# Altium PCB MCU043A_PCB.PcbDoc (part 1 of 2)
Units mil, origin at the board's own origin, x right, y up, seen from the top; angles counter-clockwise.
Board outline 3935 x 1020 mil, 2 copper layers (Top Layer, Bottom Layer), stack 62 mil thick; 69 components, 49 nets, 220 pads, 91 vias.
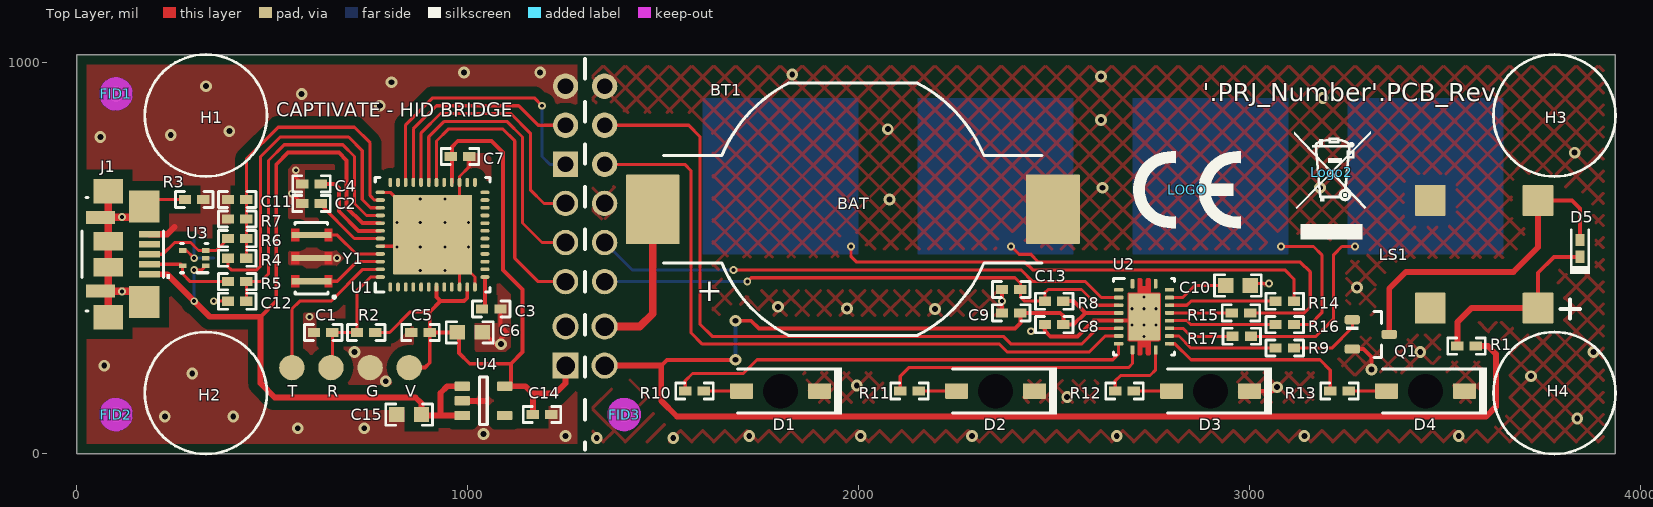
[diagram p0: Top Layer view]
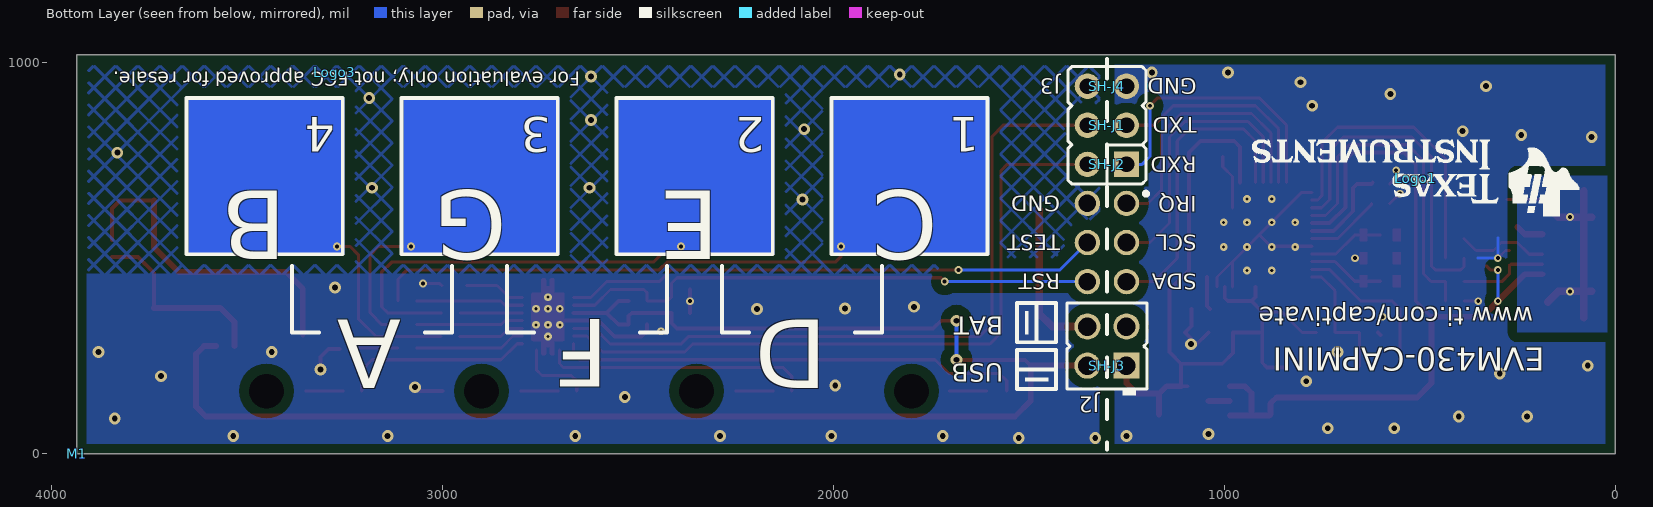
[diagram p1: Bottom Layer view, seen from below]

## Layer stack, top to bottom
Top Solder: solder mask 0.4, Solder Resist, Dk 3.5
Top Layer: signal copper 1.4
Dielectric1: core 59.2, FR-4, Dk 4.8
Bottom Layer: signal copper 1.4
Bottom Solder: solder mask 0.4, Solder Resist, Dk 3.5

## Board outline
0,0 3935,0 3935,1020 0,1020

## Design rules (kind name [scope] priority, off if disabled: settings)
AcuteAngle [All] p1: minimum=4.50000000000000E+0001 checktracksonly=FALSE
AssemblyTestPointUsage [All] p1: valid=2
BoardOutlineClearance BoardOutlineClearance_MountingHoles [OnCopper and InComponentClass('Mounting Holes')] p1: gap=40
BoardOutlineClearance BoardOutlineClearance_Poly [OnCopper and IsPoly] p2: gap=25
BoardOutlineClearance [OnCopper and Not InComponentClass('Logo') and not InComponentClass('FiducialMark') and not InRegion(1000,500,4000,800) and not InPoly] p3: gap=20
Clearance Clearance_Keepouts [((IsTrack Or IsArc) And Not InPoly) And IsFree and IsKeepOut vs ((IsTrack Or IsArc) And Not InPoly) And IsFree and IsKeepOut] p1: gap=0
Clearance Clearance_Fid [HasFootprint('Fiducial10-20')] p2: gap=0
Clearance Clearance_Poly [InPolygon] p3: gap=25
Clearance [All] p4: gap=7.87
ComponentClearance ComponentClearance-Fid [HasFootprint('Fiducial10-20')] p1: gap=10 collisioncheckmode=3 verticalgap=0 showdistances=FALSE
ComponentClearance ComponentClearance-Overlay [HasFootprint('EVM430-CAPMINI-OVERLAY-PMMA')] p2: gap=0 collisioncheckmode=3 verticalgap=0 showdistances=FALSE
ComponentClearance ComponentClearance-Jumper [HasFootprint('SPC02SYAN')] p3: gap=5 collisioncheckmode=3 verticalgap=0 showdistances=FALSE
ComponentClearance ComponentClearance_MountingHoles_FiducialMarks [InComponentClass('Mounting Holes') vs InComponentClass('FiducialMark')] p4: gap=50 collisioncheckmode=3 verticalgap=10 showdistances=FALSE
ComponentClearance ComponentClearance_Shunt [InComponentClass('Header') vs InComponentClass('Shunt')] p5: gap=0 collisioncheckmode=3 verticalgap=0 showdistances=FALSE
ComponentClearance ComponentClearance_Logo [InComponentClass('Logo')] p6: gap=50 collisioncheckmode=3 verticalgap=10 showdistances=FALSE
ComponentClearance ComponentClearance_ScrewToNut [(HasFootprint('NY PMS 440 0025 PH')) vs (HasFootprint('Keystone_1902C'))] p7: gap=5 collisioncheckmode=3 verticalgap=10 showdistances=FALSE
ComponentClearance ComponentClearance_MountingHoles [InComponentClass('Mounting Holes')] p8: gap=250 collisioncheckmode=3 verticalgap=100000 showdistances=FALSE
ComponentClearance ComponentClearance_SmallPassives [HasFootprint('0201*') or HasFootprint('0402*') or HasFootprint('0508') or HasFootprint('0603*') or HasFootprint('0612') or HasFootprint('0805*') or HasFootprint('0815*') or HasFootprint('0830*') or HasFootprint('1206*') or HasFootprint('1210*') or HasFootprint('1808*') or HasFootprint('1812*') or HasFootprint('1825*') or HasFootprint('2010*') or HasFootprint('2220*') or HasFootprint('2225*') or HasFootprint('2512*') or HasFootprint('2728*') or HasFootprint('3518*') vs HasFootprint('0201*') or HasFootprint('0402*') or HasFootprint('0508') or HasFootprint('0603*') or HasFootprint('0612') or HasFootprint('0805*') or HasFootprint('0815*') or HasFootprint('0830*') or HasFootprint('1206*') or HasFootprint('1210*') or HasFootprint('1808*') or HasFootprint('1812*') or HasFootprint('1825*') or HasFootprint('2010*') or HasFootprint('2220*') or HasFootprint('2225*') or HasFootprint('2512*') or HasFootprint('2728*') or HasFootprint('3518*')] p9: gap=14.96 collisioncheckmode=3 verticalgap=10 showdistances=FALSE
ComponentClearance ComponentClearance_THtoSMT [IsThruComponent vs IsSMTComponent] p10: gap=40 collisioncheckmode=3 verticalgap=30 showdistances=FALSE
ComponentClearance ComponentClearance_THtoTH [IsThruComponent vs IsThruComponent] p11: gap=30 collisioncheckmode=3 verticalgap=30 showdistances=FALSE
ComponentClearance [All] p12: gap=30 collisioncheckmode=3 verticalgap=10 showdistances=FALSE
DiffPairsRouting [All] p1: maxlimit=100 minlimit=10 mostfreqgap=10 toplayer_minwidth=15 toplayer_maxwidth=15 toplayer_prefwidth=15 bottomlayer_minwidth=15 bottomlayer_maxwidth=15 bottomlayer_prefwidth=15 maxuncoupledlength=1000
FabricationTestPointUsage TestPointUsage [All] p1: valid=2 allowmultiple=FALSE
FabricationTestpoint Testpoint [All] p1: side=3 testpointundercomponent=TRUE minsize=40 maxsize=100 preferedsize=60 minholesize=0 maxholesize=40 preferedholesize=32 testpointgrid=1 allowsidetop=TRUE allowsidebottom=TRUE usegrid=TRUE gridtolerance=0.01
FanoutControl Fanout_LCC [IsLCC] p1: bgadir=Out bgaviamode=Centered fanoutstyle=Auto fanoutdirection=Alternating viagrid=1 // Fanout_LCC (Default Rule)
FanoutControl Fanout_BGA [IsBGA] p2: bgadir=Out bgaviamode=Centered fanoutstyle=Auto fanoutdirection=Alternating viagrid=1 // Fanout_BGA (Default Rule)
FanoutControl Fanout_Default [All] p4: bgadir=Out bgaviamode=Centered fanoutstyle=Auto fanoutdirection=Alternating viagrid=1 // Fanout_Default (Default Rule)
FanoutControl Fanout_Small [(CompPinCount < 5)] p5: bgadir=Out bgaviamode=Centered fanoutstyle=Auto fanoutdirection=OutThenIn viagrid=1 // Fanout_Small (Default Rule)
HoleSize [All] p1: absolutevalues=TRUE maxlimit=251 minlimit=7.87 maxpercent=80.000 minpercent=20.000
MinimumAnnularRing MinimumAnnularRing_ThermalPadVias [IsVia and InAnyComponent] p1: minimumring=5
MinimumAnnularRing [All] p2: minimumring=5
MinimumSolderMaskSliver MinimumSolderMaskSliver_Logo [InComponentClass('Logo') vs InComponentClass('Logo')] p1: minsoldermaskwidth=0.7
MinimumSolderMaskSliver [All] p2: minsoldermaskwidth=3.94
PlaneConnect [All] p1: planeconnectstyle=Relief reliefexpansion=10 reliefentries=4 reliefconductorwidth=10 reliefairgap=10
PolygonConnect [All] p1: connectstyle=Direct reliefconductorwidth=10 reliefentries=4 polygonreliefangle="90 Angle" airgapwidth=10
RoutingVias ThermalPadVias [IsVia and InAnyComponent] p1: holewidth=7.87 width=19.68 viastyle="Through Hole" minholewidth=7.87 minwidth=19.68 maxholewidth=12.99 maxwidth=23.62
RoutingVias [All] p2: holewidth=16 width=34 viastyle="Through Hole" minholewidth=7.87 minwidth=20 maxholewidth=40 maxwidth=65
SilkToBoardRegionClearance [Not ((IsComment or IsDesignator) And (Hide <> 'False')) and not InRegion(1000,500,4000,800)] p1:
SilkToSilkClearance SilkToSilkClearance_Pb-FreeLogo [(HasFootprint('Pb-Free_Overlay_Medium') OR HasFootprint('Pb-Free_Overlay_Small')) vs (HasFootprint('Pb-Free_Overlay_Medium') OR HasFootprint('Pb-Free_Overlay_Small'))] p1: silktosilkclearance=0
SilkToSilkClearance [All] p2: silktosilkclearance=3
SilkToSolderMaskClearance SilkToComponentPadClearance [(IsPad or IsFill or IsRegion) and InAnycomponent] p1: minsilkscreentomaskgap=3 clearancetoexposedcopper=TRUE
SilkToSolderMaskClearance "Silk to Solder Mask Opening" [All] p2: minsilkscreentomaskgap=3 clearancetoexposedcopper=FALSE
SolderMaskExpansion [All] p1: expansion=1.97
Width [All] p1: maxlimit=100 minlimit=6 preferedwidth=10 checkconnectedcopper=TRUE
15 further rules are at their usual default settings.

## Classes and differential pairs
component class Shunt: SH-J1 SH-J2 SH-J3 SH-J4
component class MCU043A_Schematic: BT1 C1 C2 C3 C4 C5 C6 C7 C8 C9 C10 C11 C12 C13 C14 C15 D1 D2 D3 D4 D5 J1 J2 J3 LS1 Q1 R1 R2 R3 R4 R5 R6 R7 R8 R9 R10 R11 R12 R13 R14 R15 R16 R17 U1 U2 U3 U4 Y1
component class Logo: Logo1
component class MCU043A_Hardware: FID1 FID2 FID3 H1 H2 H3 H4 LOGO Logo1 Logo2 Logo3 M1 SH-J1 SH-J2 SH-J3 SH-J4 ZZ1 ZZ2 ZZ3 ZZ4 ZZ5
component class FiducialMark: FID1 FID2 FID3
component class AssemblyNote: ZZ1 ZZ2 ZZ3 ZZ4 ZZ5
component class Header: J2 J3

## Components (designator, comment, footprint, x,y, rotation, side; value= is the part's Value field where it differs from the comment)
BT1 "BU1632SM-JJ-GTR" MPD_BU1632SM-JJ-GTR 1985,625 r0 top
C1 "GRM155R61A102KA01D" 0402 630,310 r180 top
C2 "GRM155R61A224KE19D" 0402 600,640 r180 top
C3 "GRM155R61A474KE15D" 0402 1060,370 r0 top
C4 "GRM155R61A224KE19D" 0402 600,690 r180 top
C5 "GRM155R61C104KA88D" 0402 878.94,310 r180 top
C6 "GRM188R61A475MAAJ" 0603 1005,310 r0 top
C7 "GRM155R61C104KA88D" 0402 980,760 r0 top
C8 "GRM155R61E104KA87D" 0402 2500,330 r180 top
C9 "GRM155R60J475ME87D" 0402 2390,360 r180 top
C10 "GRM185R60J105KE26D" 0603 2970,430 r0 top
C11 "GRM1555C1H100JA01D" 0402 410,650 r180 top
C12 "GRM1555C1H100JA01D" 0402 410,390 r180 top
C13 "GRM155R61A102KA01D" 0402 2390,420 r180 top
C14 "GRM155R61C104KA88D" 0402 1190,100 r0 top
C15 "GRM188R61A475MAAJ" 0603 850,100 r180 top
D1 "AM2520SURCK09" AM2520_Red 1800,160 r0 top
D2 "AM2520SURCK09" AM2520_Red 2350,160 r0 top
D3 "AM2520SURCK09" AM2520_Red 2900,160 r0 top
D4 "AM2520SURCK09" AM2520_Red 3450,160 r0 top
D5 "1N4148X-TP" SOD-523 3845,525 r90 top
FID1 "Fiducial" Fiducial10-20 100,920 r0 top
FID2 "Fiducial" Fiducial10-20 100,100 r0 top
FID3 "Fiducial" Fiducial10-20 1400,100 r0 top
H1 "SJ61A1" Bumpon_SJ61A1 330,865 r90 top
H2 "SJ61A1" Bumpon_SJ61A1 330,155 r90 top
H3 "SJ61A1" Bumpon_SJ61A1 3780,865 r90 top
H4 "SJ61A1" Bumpon_SJ61A1 3780,155 r90 top
J1 "ZX62R-B-5P(30)" Hirose_ZX62R-B-5P 80,510 r180 top
J2 "PBC02DAAN" Sullins_PxC02DAAN 1300,275 r0 bottom
J3 "PBC03DAAN" Sullins_PBC03DAAN 1300,840 r0 bottom
LOGO "CE Mark" CE_Mark_5mm 2840,675 r0 top
Logo1 "Texas Instruments" TI_Stacked_Overlay_Small 510,705 r0 bottom
Logo2 "WEEE logo" WEEE_Minimum 3210,720 r0 top
Logo3 "FCC disclaimer" FCC_disclaimer 3275,975 r0 bottom
LS1 "ST-03BL" Soberton_ST-03BL 3600,510 r180 top
M1 "MCH015A" EVM430-CAPMINI-OVERLAY-PMMA 3935,0 r180 bottom
Q1 "MMBT3904" SOT-23 3310,305 r0 top
R1 "CRCW040230R0JNED" 0402 3555,275 r0 top
R2 "CRCW040247K0JNED" 0402 740,310 r0 top
R3 "CRCW040233R0JNED" 0402 300,650 r0 top
R4 "CRCW04021K50JNED" 0402 410,500 r180 top
R5 "CRCW040227R0JNED" 0402 410,440 r0 top
R6 "CRCW040227R0JNED" 0402 410,550 r0 top
R7 "CRCW04021M00JNED" 0402 410,600 r0 top
R8 "CRCW040247K0JNED" 0402 2500,390 r0 top
R9 "CRCW0402180RJNED" 0402 3090,270 r0 top
R10 "CRCW04024K70JNED" 0402 1580,160 r180 top
R11 "CRCW04024K70JNED" 0402 2130,160 r180 top
R12 "CRCW04024K70JNED" 0402 2680,160 r180 top
R13 "CRCW04024K70JNED" 0402 3230,160 r180 top
R14 "CRCW0402470RJNED" 0402 3090,390 r180 top
R15 "CRCW0402470RJNED" 0402 2978.19,360 r180 top
R16 "CRCW0402470RJNED" 0402 3090,330 r180 top
R17 "CRCW0402470RJNED" 0402 2980,300 r180 top
SH-J1 "SPC02SYAN" SPC02SYAN 1300,840 r180 bottom
SH-J2 "SPC02SYAN" SPC02SYAN 1300,740 r180 bottom
SH-J3 "SPC02SYAN" SPC02SYAN 1300,225 r180 bottom
SH-J4 "SPC02SYAN" SPC02SYAN 1300,940 r0 bottom
U1 "MSP430F5510IRGZT" RGZ0048A 910,560 r90 top
U2 "MSP430FR2512IRHLT" RHL0020A 2730,350 r0 top
U3 "TPD2E001DRLR" DRL0005A 300,500 r180 top
U4 "TLV70233DBVR" DBV0005A_N 1040,135 r0 top
Y1 "CSTCR4M00G15L99-R0" Murata_CSTCR 600,500 r90 top
ZZ1 "This Assembly Note is for PCB labels only" AssemblyNoteLabel -605,2448 r0 top
ZZ2 "These assemblies are ESD sensitive, ESD precautions shall be observed." AssemblyNote -600,2340 r0 top
ZZ3 "These assemblies must be clean and free from flux and all contaminants. Use of no clean flux is not acceptable." AssemblyNote -605,2230 r0 top
ZZ4 "These assemblies must comply with workmanship standards IPC-A-610 Class 2, unless otherwise specified." AssemblyNote -605,2115 r0 top
ZZ5 "Overlay Assembly Notes  Component 'M1' represents the keypad overlay dielectric assembly.    The adhesive shall be cut to the same pattern as the plastic, and attached to the back of the plastic.  Then, the overlay plastic shall be bonded to the bottom layer of the PCB.     For a detailed drawing of the overlay, see MCH015A_Mech.pdf" AssemblyNote 3707,-545 r180 bottom

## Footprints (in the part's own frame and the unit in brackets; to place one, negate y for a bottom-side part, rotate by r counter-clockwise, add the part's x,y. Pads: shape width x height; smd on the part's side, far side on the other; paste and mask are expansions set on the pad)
0402 [mm] "0402 from SM-752 data"
  rect 0.8x0.6 smd: 1(-0.6,0) 2(0.6,0)
  silkscreen extent -1.22,-0.52 1.22,0.52, body extent -0.55,-0.3 0.55,0.3, height 0.6
0603 [mm] "0603 from SM-752 data"
  rect 1x0.95 smd: 1(-0.8,0) 2(0.8,0)
  silkscreen extent -1.52,-0.69 1.52,0.69, body extent -0.87,-0.47 0.87,0.47, height 1
AM2520_Red [mm] "SMD, 2-Leads, Body 2.5x2mm"
  rrect10% 1.5x1 smd: 1(-2.525,0) 2(2.525,0)
  round 0 hole 2.25 unplated: ""(0,0)
  silkscreen extent -2.8,-1.53 4,1.53, body extent -2.8,-1 3,1, height 1.4
AssemblyNote [mil] "Assembly Note"
AssemblyNoteLabel [mil] "Assembly Note for PCB Labels"
Bumpon_SJ61A1 [mil] "3M Cylindrical Bumpon black"
  round 1 on Mech3: 0(0,0)
  silkscreen extent -156,-156 156,156, body extent -156,-155 156,156, height 201
CE_Mark_5mm [mil] "Minimum text height for CE Mark"
  silkscreen extent -138,-98 138,98
DBV0005A_N [mm] "SOT23, 5-Leads, Body 2.9x1.6mm, Pitch 0.95mm, Lead Span 2.8mm, IPC Medium Density"
  rrect17% 1x0.6 smd: 1(-1.375,0.95) 2(-1.375,0) 3(-1.375,-0.95) 4(1.375,-0.95) 5(1.375,0.95)
  silkscreen extent -0.25,-1.55 0.25,1.55, body extent -1.42,-1.46 1.42,1.46, height 1.09
DRL0005A [mm] "SOTFL, 5-Flat Leads, Body 1.2x1.6x0.6mm, Pitch 0.5mm, TI recommended"
  rect 0.5x0.3 smd: 1(-0.75,0.5) 2(-0.75,0) 3(-0.75,-0.5) 4(0.75,-0.5) 5(0.75,0.5)
  silkscreen extent -0.9,-0.95 0.9,0.95, body extent -0.85,-0.85 0.85,0.85, height 0.62
EVM430-CAPMINI-OVERLAY-PMMA [mil] "EVM430-CAPMINI-OVERLAY-PMMA"
  body extent 0,0 2520,1020, height 79
FCC_disclaimer [mil]
Fiducial10-20 [mm]
  round 1 smd mask+0.5: 1(0,0)
  Top Layer keep-out circle w1.178: c0,0 r0.5
Hirose_ZX62R-B-5P [mm] "Hirose"
  rect 1.35x0.4 smd: 1(-2.68,1.3) 2(-2.68,0.65) 3(-2.68,0) 4(-2.68,-0.65) 5(-2.68,-1.3)
  rect 2x2.1 smd: 6(-2.35,-3.1) 7(-2.35,3.1)
  rect 1.9x1.6 smd: 8(0,-4.1) 13(0,4.1)
  rect 1.88x0.85 smd: 9(0.495,-2.4) 12(0.495,2.4)
  rect 1.9x1.2 smd: 10(0,-0.85) 11(0,0.85)
  silkscreen extent -4,-3.67 1.7,3.67, body extent -2.57,-3.48 2.11,3.45, height 2.65
MPD_BU1632SM-JJ-GTR [mm] "SMD, 2-Leads, Body 27.7x16.4mm"
  rrect3% 3.5x4.5 smd: 1(-13,0) 2(13,0)
  silkscreen extent -12.3,-8.2 12.3,8.2, body extent -13.91,-8.2 13.91,8.2, height 5.2
Murata_CSTCR [mm] "Murata"
  rect 0.4x2.6 smd mask+0.051: 1(-1.5,0) 2(0,0) 3(1.5,0)
  Top Layer region: 1.1,-1.35 1.1,-0.85 1.9,-0.85 1.9,-1.35
  Top Layer region: 1.1,-1.35 1.1,-0.85 1.9,-0.85 1.9,-1.35
  Top Layer region: 1.1,0.8 1.9,0.8 1.9,1.3 1.1,1.3
  Top Layer region: -1.9,-1.35 -1.9,-0.85 -1.1,-0.85 -1.1,-1.35
  Top Layer region: -1.9,-1.35 -1.9,-0.85 -1.1,-0.85 -1.1,-1.35
  Top Layer region: -1.9,0.8 -1.1,0.8 -1.1,1.3 -1.9,1.3
  Top Layer region: -0.4,-1.35 -0.4,-0.85 0.4,-0.85 0.4,-1.35
  Top Layer region: -0.4,-1.35 -0.4,-0.85 0.4,-0.85 0.4,-1.35
  Top Layer region: -0.4,0.8 0.4,0.8 0.4,1.3 -0.4,1.3
  silkscreen extent -2.61,-1.56 2.32,1.08, body extent -2.3,-1.05 2.3,1.05, height 1.2
RGZ0048A [mm] "QFN, 48-Leads, Body 7x7mm, Pitch 0.5mm, Thermal Pad 5.15X5.15mm, TI recommended"
  rrect100% 0.6x0.24 smd: 1(-3.4,2.75) 2(-3.4,2.25) 3(-3.4,1.75) 4(-3.4,1.25) 5(-3.4,0.75) 6(-3.4,0.25) 7(-3.4,-0.25) 8(-3.4,-0.75) 9(-3.4,-1.25) 10(-3.4,-1.75) 11(-3.4,-2.25) 12(-3.4,-2.75) 25(3.4,-2.75) 26(3.4,-2.25) 27(3.4,-1.75) 28(3.4,-1.25) 29(3.4,-0.75) 30(3.4,-0.25) 31(3.4,0.25) 32(3.4,0.75) 33(3.4,1.25) 34(3.4,1.75) 35(3.4,2.25) 36(3.4,2.75)
  rrect100% 0.24x0.6 smd: 13(-2.75,-3.4) 14(-2.25,-3.4) 15(-1.75,-3.4) 16(-1.25,-3.4) 17(-0.75,-3.4) 18(-0.25,-3.4) 19(0.25,-3.4) 20(0.75,-3.4) 21(1.25,-3.4) 22(1.75,-3.4) 23(2.25,-3.4) 24(2.75,-3.4) 37(2.75,3.4) 38(2.25,3.4) 39(1.75,3.4) 40(1.25,3.4) 41(0.75,3.4) 42(0.25,3.4) 43(-0.25,3.4) 44(-0.75,3.4) 45(-1.25,3.4) 46(-1.75,3.4) 47(-2.25,3.4) 48(-2.75,3.4)
  rrect2% 5.15x5.15 smd paste-2.6: 49(0,0)
  silkscreen extent -3.72,-3.72 3.72,3.72, body extent -3.58,-3.57 3.57,3.58, height 1.01
RHL0020A [mm] "QFN, 20-Leads, Body 4.5x3.5mm, Pitch 0.5mm, Thermal Pad 3.05x2.05mm, TI Recommended"
  rrect42% 0.24x0.6 smd: 1(-0.75,2.15) 10(-0.75,-2.15) 11(0.75,-2.15) 20(0.75,2.15)
  rrect42% 0.6x0.24 smd: 2(-1.65,1.75) 3(-1.65,1.25) 4(-1.65,0.75) 5(-1.65,0.25) 6(-1.65,-0.25) 7(-1.65,-0.75) 8(-1.65,-1.25) 9(-1.65,-1.75) 12(1.65,-1.75) 13(1.65,-1.25) 14(1.65,-0.75) 15(1.65,-0.25) 16(1.65,0.25) 17(1.65,0.75) 18(1.65,1.25) 19(1.65,1.75)
  rrect12% 0.92x0.85 on Top Paste: 21(-0.56,-1.05) 21(-0.56,0) 21(-0.56,1.05) 21(0.56,-1.05) 21(0.56,0) 21(0.56,1.05)
  rrect5% 2.05x3.05 smd paste-2 mask+0: 21(0,0)
  Top Layer region: -0.975,-1.575 -0.425,-1.575 -0.425,-2.4 -0.417,-2.438 -0.396,-2.471 -0.363,-2.492 -0.325,-2.5 -0.325,-2.5 -0.225,-2.5 -0.187,-2.492 -0.154,-2.471 -0.133,-2.438 -0.125,-2.4 -0.125,-2.4 -0.125,-1.975 0.125,-1.975 0.125,-2.4 0.133,-2.438 0.154,-2.471 0.187,-2.492 0.225,-2.5 0.225,-2.5 0.325,-2.5 0.363,-2.492 0.396,-2.471 0.417,-2.438 0.425,-2.4 0.425,-2.4 0.425,-1.575 0.975,-1.575 1.013,-1.567 1.046,-1.546 1.067,-1.513 1.075,-1.475 1.075,-1.475 1.075,1.475 1.067,1.513 1.046,1.546 1.013,1.567 0.975,1.575 0.975,1.575 0.425,1.575 0.425,2.4 0.417,2.438 0.396,2.471 0.363,2.492 0.325,2.5 0.325,2.5 0.225,2.5 0.187,2.492 0.154,2.471 0.133,2.438 0.125,2.4 0.125,2.4 0.125,1.975 -0.125,1.975 -0.125,2.4 -0.133,2.438 -0.154,2.471 -0.187,2.492 -0.225,2.5 -0.225,2.5 -0.325,2.5 -0.363,2.492 -0.396,2.471 -0.417,2.438 -0.425,2.4 -0.425,2.4 -0.425,1.575 -0.975,1.575 -1.013,1.567 -1.046,1.546 -1.067,1.513 -1.075,1.475 -1.075,1.475 -1.075,-1.475 -1.067,-1.513 -1.046,-1.546 -1.013,-1.567 -0.975,-1.575
  silkscreen extent -1.98,-2.47 1.98,2.47, body extent -1.75,-2.25 1.75,2.25, height 1.01
Soberton_ST-03BL [mm] "SMD, 4-Leads, Body 8.5x8.5mm"
  rrect5% 2x2 smd: 1(-3.5,3.5) 2(-3.5,-3.5) 3(3.5,-3.5) 4(3.5,3.5)
  body extent -4.2,-4.2 4.2,4.2, height 2.9
SOD-523 [mm] "NXP Semiconductor recommended land pattern, nominal STEP model"
  rect 0.8x0.6 smd paste-0.05: 1(-0.55,0) 2(0.55,0)
  silkscreen extent -1.65,-0.66 1.2,0.66, body extent -0.8,-0.4 0.8,0.4, height 0.72
SOT-23 [mm] "SOT23, 3-Leads, Body 2.9x1.3mm, Pitch 0.95mm, Lead Span 2.5mm, IPC Medium Density"
  rrect50% 1x0.6 smd: 1(-1.2,0.95) 2(-1.2,-0.95) 3(1.2,0)
  silkscreen extent -1.63,-1.5 0.7,1.5, body extent -1.16,-1.45 1.21,1.45, height 1
SPC02SYAN [mil] "SULLINS"
  round 1 on Mech4: 0(0,0)
  body extent -98,-47 99,47, height 366
Sullins_PBC03DAAN [mm] "Sullins 100mil, 2x3, 230 mil above insulator"
  rect 1.65x1.65 hole 1.016: 1(-1.27,2.54)
  round 1.65 hole 1.016: 2(1.27,2.54) 3(-1.27,0) 4(1.27,0) 5(-1.27,-2.54) 6(1.27,-2.54)
  silkscreen extent -2.67,-3.81 2.54,4.58, body extent -2.54,-3.81 2.54,3.81, height 8.38
Sullins_PxC02DAAN [mm] "Header, 2.54mm, 2x2, TH"
  rect 1.7x1.7 hole 1.2: 1(-1.27,1.27)
  round 1.7 hole 1.2: 2(1.27,1.27) 3(-1.27,-1.27) 4(1.27,-1.27)
  silkscreen extent -2.61,-2.8 2.61,3.2, body extent -2.61,-2.8 2.61,2.8, height 8.58
TI_Stacked_Overlay_Small [mil]
  silkscreen extent -418,-98 418,98
WEEE_Minimum [mil] "WEEElie bin"
  silkscreen extent -95,-172 99,104

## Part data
BT1: library part CMP-0078509-1, "HOLDER COIN CELL 1632 GOLD, SMD"
C1 C13: "CAP, CERM, 1000 pF, 10 V,+/- 10%, X5R, 0402"
C2 C4: library part CMP-0006570-2, "CAP, CERM, 0.22 uF, 10 V, +/- 10%, X5R, 0402"
C3: library part CMP-0006580-2, "CAP, CERM, 0.47 uF, 10 V, +/- 10%, X5R, 0402"
C5 C7 C14: library part CMP-0006591-2, "CAP, CERM, 0.1 uF, 16 V, +/- 10%, X5R, 0402"
C6 C15: library part CMP-0007329-5, "CAP, CERM, 4.7 uF, 10 V, +/- 20%, X5R, 0603"
C8: library part CMP-0006607-2, "CAP, CERM, 0.1 uF, 25 V, +/- 10%, X5R, 0402"
C9: library part CMP-0006553-2, "CAP, CERM, 4.7 uF, 6.3 V, +/- 20%, X5R, 0402"
C10: library part CMP-0007155-5, "CAP, CERM, 1 uF, 6.3 V, +/- 10%, X5R, 0603"
C11 C12: "CAP, CERM, 10pF, 50V, +/-5%, C0G/NP0, 0402"
D1 D2 D3 D4: "LED, Red, SMD"
D5: library part CMP-0076957-2, "Diode, Switching, 75 V, 0.3 A, SOD-523"
FID1 FID2 FID3: "Fiducial mark.  There is nothing to buy or mount."
H1 H2 H3 H4: "Bumpon, Cylindrical, 0.312 X 0.200, Black"
J1: library part CMP-0079906-1, "Connector, Receptacle, Micro-USB Type B, Top Mount SMT"
J2: library part CMP-0054598-1, "Header, 2.54mm, 2x2, Gold, TH"
J3: library part CMP-0054565-1, "Header, 100mil, 3x2, Gold, TH"
Logo1: library part TI_Logo, "Texas Instrument Corporate Signature"
Logo2: library part CMP-0074769-1
Logo3: library part FCC_disclaimer, "FCC_disclaimer"
LS1: library part CMP-0078858-1, "Magnetic Transducer, SMD"
M1: library part EVM430-CAPMINI-OVERLAY-PMMA, "EVM430-CAPMINI Overlay Plastic"
Q1: library part "MMBT3904, Fairchild Semiconductor", "Transistor, NPN, 40 V, 0.2 A, SOT-23"
R1: library part CMP-0026904-3, "RES, 30, 5%, 0.063 W, AEC-Q200 Grade 0, 0402"
R2 R8: "RES, 47k ohm, 5%, 0.063W, 0402"
R3: "RES, 33, 5%, 0.063 W, 0402"
R4: "RES, 1.5 k, 5%, 0.063 W, 0402"
R5 R6: "RES, 27 ohm, 5%, 0.063W, 0402"
R7: "RES, 1.0 M, 5%, 0.063 W, 0402"
R9: "RES, 180, 5%, 0.063 W, 0402"
R10 R11 R12 R13: library part CMP-0026938-5, "RES, 4.7 k, 5%, 0.063 W, AEC-Q200 Grade 0, 0402"
R14 R15 R16 R17: "RES, 470, 5%, 0.063 W, 0402"
SH-J1 SH-J2 SH-J3 SH-J4: "Shunt, 100mil, Flash Gold, Black"
U1: "25 MHz Mixed Signal Microcontroller with 32 KB Flash, 4096 B SRAM and 47 GPIOs, -40 to 85 degC, 48-pin QFN (RGC), Green (RoHS & no Sb/Br)"
U2: library part CMP-0078346-1, "Capacitive Touch Sensing Mixed-Signal Microcontroller, RHL0020A (VQFN-20)"
U3: "Low-Capacitance + / - 15 kV ESD-Protection Array for High-Speed Data Interfaces, 2 Channels, -40 to +85 degC, 5-pin SOT (DRL), Green (RoHS & no Sb/Br)"
U4: library part CMP-0035516-1, "Single Output LDO, 300 mA, Fixed 3.3 V Output, 2 to 5.5 V Input, with Low IQ, 5-pin SOT-23 (DBV), -40 to 125 degC, Green (RoHS & no Sb/Br)"
Y1: "Resonator, 4 MHz, 39pF SMD"
ZZ1: library part AssemblyNoteLabel
ZZ2 ZZ3 ZZ4 ZZ5: library part AssemblyNote

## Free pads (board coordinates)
  round 65 smd: 1(550,220) 1(650,220) 1(750,220) 1(850,220)
  round 65 hole 45: 1(1250,440) 1(1250,540) 1(1250,640) 1(1350,440) 1(1350,540) 1(1350,640)

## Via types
v1: diameter 30, hole 15, Top Layer to Bottom Layer, tented both sides, 51 vias
v2: diameter 19.68, hole 7.87, Top Layer to Bottom Layer, 20 vias
v3: diameter 20, hole 10, Top Layer to Bottom Layer, tented both sides, 20 vias

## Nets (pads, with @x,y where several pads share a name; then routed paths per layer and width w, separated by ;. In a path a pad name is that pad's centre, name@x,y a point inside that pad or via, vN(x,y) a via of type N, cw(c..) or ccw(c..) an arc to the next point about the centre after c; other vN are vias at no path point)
+3V3: C4.1 U1.42 | length 242.6
  Top Layer w10: C4.1@620,693.62 C4.1@623.62,690 660,690 670,680 670,620 720.16,569.84 U1.42@776.14,569.84
+3V3_Target: C8.1 C9.1 J2.2 R1.2 R8.2 U2.5 | length 4019.5
  Top Layer w10: 1495,225 1510,240 v1(1685,240) ; v1(1685,340) 1725,340 1745,320 2399.99,320 2413.62,333.63 C9.1@2413.62,360 2515.5,360 2523.62,351.88 C8.1@2523.62,330 2550,330 2579.84,359.84 ; R8.2@2523.62,390 2549.68,390 2579.84,359.84 ; U2.5@2665.04,359.84 2579.84,359.84
  Top Layer w15: J2.2@1350,225 1495,225 1495,135 1535,95 3605,95 3630,120 3630,255 3610,275 R1.2@3578.62,275
  Bottom Layer w10: v1@1685,235 v1(1685,340)
+VBUS: C15.1 J1.1 U1.41 U3.1 U4.1 U4.3 | length 2130.7
  Top Layer w8: v3(300,470) 319.21,470 U3.1@329.53,480.31
  Top Layer w10: 470,350 510,390 510,740 540,770 670,770 690,750 690,630 730.47,589.53 U1.41@776.14,589.53
  Top Layer w15: J1.1@185.51,458.82 231.18,458.82 v3(300,390) 340,350 470,350 470,180 506.3,143.7 866.3,143.7 881.5,128.5 C15.1@881.5,100 883.9,97.6 930,97.6 ; U4.3@985.87,97.6 930,97.6 ; U4.1@985.87,172.4 947.4,172.4 930,155 930,97.6
  Bottom Layer w8: v3(300,390) v3(300,470)
+VLDO: C5.1 C6.1 C7.1 C14.1 J2.1 pad.1@850,220 R2.2 U1.7 U1.11 U1.28 U4.5 | length 1942
  Top Layer w8: R2.2@763.62,310 800,310 852.56,362.56 902.56,362.56
  Top Layer w10: pad.1@850,220 890,220 902.56,232.56 C5.1@902.56,310 ; U1.7@919.84,426.14 919.84,400.16 930,390 ; U1.28@959.21,693.86 959.21,784.21 974.21,799.21 1060.79,799.21 1090,770 1090,470 1140,420 1140,260 1110,230 ; U1.11@998.58,426.14 998.58,398.58 990,390 930,390 ; U4.5@1094.13,172.4 1110,172.4 1110,230 ; C5.1@902.56,310 902.56,362.56 930,390 ; C5.1@902.56,310 C6.1@973.5,310 977.44,310 977.44,257.56 1005,230 1110,230
  Top Layer w15: U4.5@1110,172.4 1147.6,172.4 1166.38,153.62 ; C14.1@1166.38,100 1166.38,153.62 ; J2.1@1250,225 1250,180 1223.62,153.62 1166.38,153.62
Battery: BT1.1 J2.4 | length 403.7
  Top Layer w20: J2.4@1350,325 1440,325 1473.19,358.19 BT1.1@1473.19,625
BRIDGE_DM: C12.1 R5.2 U1.40 | length 852.6
  Top Layer w8: C12.1@433.62,390 R5.2@433.62,440 470,440 490,460 490,750 530,790 680,790 710,760 710,640 740.79,609.21 U1.40@776.14,609.21
BRIDGE_DP: C11.1 R4.1 R6.2 R7.2 U1.38 | length 786.1
  Top Layer w8: R4.1@433.62,500 R7.2@433.62,600 C11.1@433.62,650 433.62,753.62 515,835 710,835 750,795 750,660 761.42,648.58 U1.38@776.14,648.58
BRIDGE_PUR: R4.2 U1.39 | length 868.1
  Top Layer w8: R4.2@386.38,500 386.38,478.12 394.5,470 460,470 470,480 470,760 520,810 695,810 730,775 730,650 751.1,628.9 U1.39@776.14,628.9
BRIDGE_RST: C1.1 pad.1@650,220 R2.1 U1.48 | length 329.9
  Top Layer w8: pad.1@653.62,223.62 C1.1@653.62,310 R2.1@716.38,310 716.38,416.38 751.73,451.73 U1.48@776.14,451.73
BRIDGE_RXD: J3.1 U1.34 | length 731.2
  Top Layer w8: U1.34@841.1,693.86 841.1,841.1 910,910 1170,910 v3(1190,890)
  Bottom Layer w8: v3(1190,890) 1190,760 1210,740 J3.1@1250,740
BRIDGE_SCL: pad.1@1250,540 U1.31 | length 739.9
  Top Layer w8: U1.31@900.16,693.86 900.16,810.16 940,850 1100,850 1140,810 1140,590 1190,540 pad.1@1250,540
BRIDGE_SDA: pad.1@1250,440 U1.30 | length 785.9
  Top Layer w8: U1.30@919.84,693.86 919.84,799.84 950,830 1090,830 1120,800 1120,500 1180,440 pad.1@1250,440
BRIDGE_TEST: pad.1@550,220 U1.47 | length 418.2
  Top Layer w8: pad.1@550,220 550,370 570,390 650,390 731.42,471.42 U1.47@776.14,471.42
BRIDGE_TXD: J3.3 U1.33 | length 571.4
  Top Layer w8: U1.33@860.79,693.86 860.79,830.79 920,890 1130,890 1180,840 J3.3@1250,840
BRIDGE_V18: C2.1 U1.43 | length 191.9
  Top Layer w8: C2.1@623.62,640 623.62,636.38 709.84,550.16 U1.43@776.14,550.16
BRIDGE_VCORE: C3.1 U1.13 | length 84.8
  Top Layer w10: C3.1@1036.38,370 1043.86,377.48 U1.13@1043.86,451.73
Buzzer: R9.1 U2.13 | length 284.2
  Top Layer w8: U2.13@2794.96,300.79 2819.21,300.79 2850,270 R9.1@3066.38,270
CAP1: R14.1 | length 1239.3
  Top Layer w8: v3(1980,530) 1980,505 1995,490 2425,490 2445,470 3090,470 3113.62,446.38 R14.1@3113.62,390
CAP2: R15.1 | length 1041.3
  Top Layer w8: v3(2390,530) 2410,510 2440,510 2460,490 3130,490 3155,465 3155,375 3140,360 R15.1@3001.81,360
CAP3: R16.1 | length 346.1
  Top Layer w8: v3(3080,530) 3163.37,530 3185,508.37 3185,360 3155,330 R16.1@3113.62,330
CAP4: R17.1 | length 457.7
  Top Layer w8: R17.1@3003.62,300 3170,300 3215,345 3215,509 3236,530 v3(3270,530)
D+: J1.3 R6.1 U3.3 | length 234.3
  Top Layer w8: J1.3@185.51,510 220,510 250,540 290.94,540 311.25,519.68 U3.3@329.53,519.68 356.06,519.68 R6.1@386.38,550
D-: J1.2 R5.1 U3.5 | length 231.4
  Top Layer w8: J1.2@185.51,484.41 266.38,484.41 U3.5@270.47,480.31 270.47,459.53 290,440 R5.1@386.38,440
FR2512_RXD: J3.4 U2.7 | length 1844.9
  Top Layer w8: J3.4@1350,840 1565.1,840 1594.13,810.97 1594.13,331.03 1625.16,300 2370,300 2390,280 2570,280 2610.47,320.47 U2.7@2665.04,320.47
FR2512_SBWTCK_TST: pad.1@1350,540 U2.3 | length 1373.4
  Top Layer w8: v3(1680,470) 2415,470 2445,440 2580,440 2620.79,399.21 U2.3@2665.04,399.21
  Bottom Layer w8: pad.1@1350,540 1420,470 v3(1680,470)
FR2512_SBWTDIO_RST: C13.1 pad.1@1350,440 R8.1 U2.4 | length 1406.8
  Top Layer w8: v3(1715,440) 1725,450 2400,450 2413.62,436.38 C13.1@2413.62,420 2413.62,400.88 2424.5,390 R8.1@2476.37,390 2476.37,411.88 2484.5,420 2570,420 2610.47,379.53 U2.4@2665.04,379.53
  Bottom Layer w8: pad.1@1350,440 v3(1715,440)
FR2512_TXD: J3.2 U2.8 | length 1773.9
  Top Layer w8: J3.2@1350,740 1555,740 1571,724 1571,309 1600,280 2360,280 2380,260 2590,260 2630.78,300.79 U2.8@2665.04,300.79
